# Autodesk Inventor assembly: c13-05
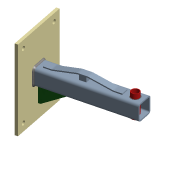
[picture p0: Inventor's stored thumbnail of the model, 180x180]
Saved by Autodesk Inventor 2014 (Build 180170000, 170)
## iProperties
Created: 2011-01
Part Number: c13-05
Document SubType Name: Weldment
Designer: Thom Tremblay
Weld Material: Welded Steel Mild
_SolveAssemblyDoc: Frame Generator Solve Assembly
_Version: 15.0.0
Author: Thom Tremblay
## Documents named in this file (5)
- C:\Inventor 2014 Essentials\Assemblies\Chapter 13\c13-05.iam
- C:\Inventor 2014 Essentials\Parts\Chapter 13\c13-01.ipt
- C:\Inventor 2014 Essentials\Parts\Chapter 13\c13-02.ipt
- C:\Inventor 2014 Essentials\Assemblies\Chapter 13\Frame\Frame c13-01.iam
- C:\Inventor 2014 Essentials\Parts\Chapter 13\c13-03.ipt
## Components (4 placed, 4 different names)
1. c13-01:1 — Mate:2
2. c13-02:1 — Flush:1
3. Frame c13-01:1 [sub-assembly] — Mate:3
4. c13-03:1 — Mate:1, Mate:2, Mate:3
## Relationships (4: Mate 3, Flush 1)
- Flush:1: c13-02:1
- Mate:1: c13-03:1
- Mate:2: c13-01:1 ↔ c13-03:1
- Mate:3: Frame c13-01:1 ↔ c13-03:1
